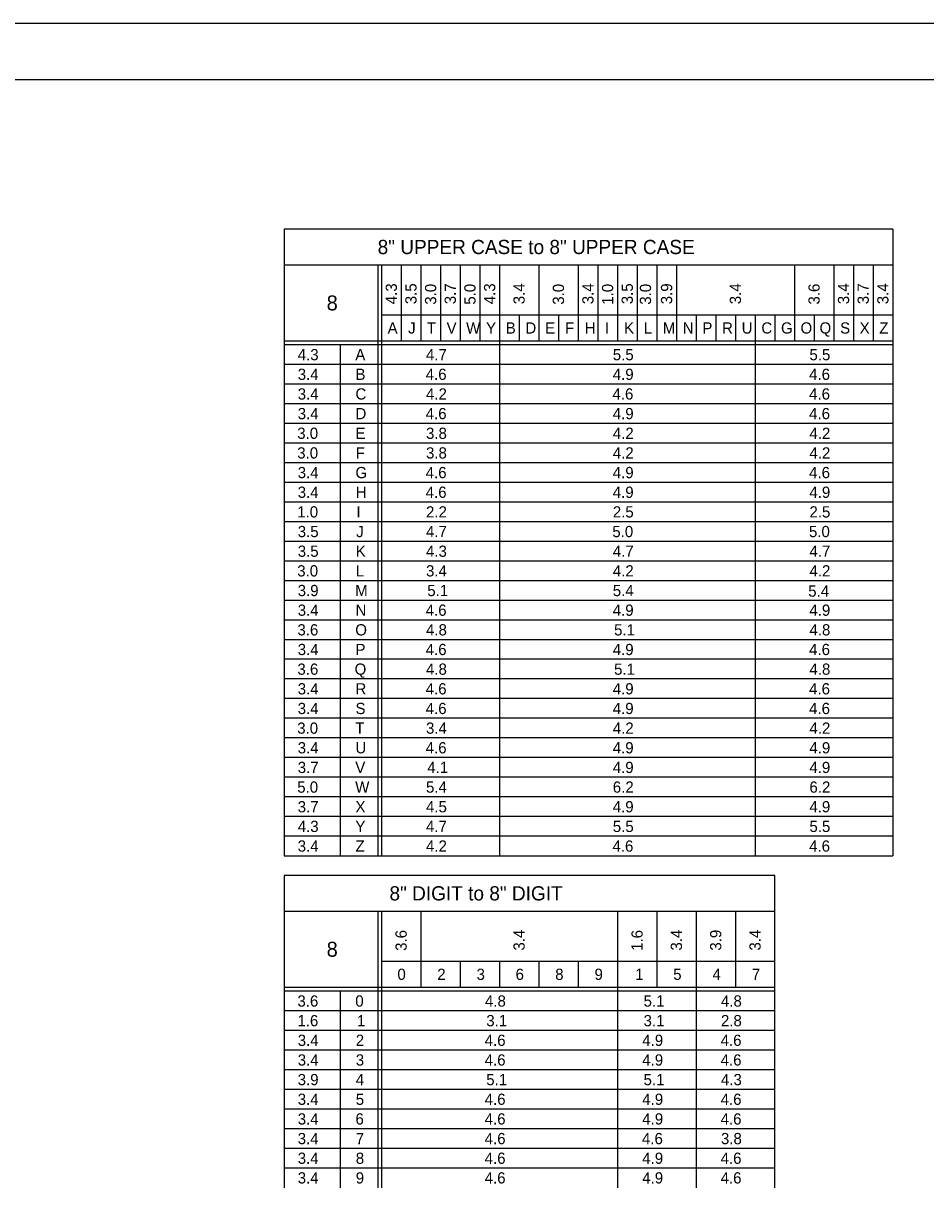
# Model space of a CAD drawing. Extents: x 638421 to 641849, y 297270 to 299646.
# Drawn here: x 641226.4 to 641467.4, y 299334.6 to 299645.6 of the extents above; entities that cross this region are included whole.
import ezdxf

# ---------------------------------------------------------------- set-up
doc = ezdxf.new("R2010")
doc.units = 0
for name, color, linetype in [('1', 7, 'Continuous'), ('2', 7, 'Continuous'), ('XCS-GRID-HVGL', 7, 'Continuous')]:
    doc.layers.add(name, color=color, linetype=linetype)

msp = doc.modelspace()

# ---------------------------------------------------------------- linework, layer by layer
at = {"layer": '1'}
msp.add_line((640984.31, 299630.63), (641770.31, 299630.63), dxfattribs=at)
at = {"layer": '2'}
for p, q in [((641458.56, 299590.63), (641296.06, 299590.63)), ((641296.06, 299590.63), (641296.06, 299423.25)), ((641458.56, 299590.63), (641458.56, 299423.25)), ((641296.06, 299581.13), (641458.56, 299581.13)), ((641321.06, 299581.13), (641321.06, 299423.25)), ((641322.06, 299581.13), (641322.06, 299423.25)), ((641327.31, 299581.13), (641327.31, 299560.75)), ((641332.56, 299581.13), (641332.56, 299560.75)), ((641337.81, 299581.13), (641337.81, 299560.75)), ((641343.06, 299581.13), (641343.06, 299560.75)), ((641348.31, 299581.13), (641348.31, 299560.75)), ((641353.56, 299581.13), (641353.56, 299423.25)), ((641364.06, 299581.13), (641364.06, 299560.75)), ((641374.56, 299581.13), (641374.56, 299560.75)), ((641379.81, 299581.13), (641379.81, 299560.75)), ((641385.06, 299581.13), (641385.06, 299560.75)), ((641390.31, 299581.13), (641390.31, 299560.75)), ((641395.56, 299581.13), (641395.56, 299560.75)), ((641400.81, 299581.13), (641400.81, 299560.75)), ((641432.31, 299581.13), (641432.31, 299560.75)), ((641442.81, 299581.13), (641442.81, 299560.75)), ((641448.06, 299581.13), (641448.06, 299560.75)), ((641453.31, 299581.13), (641453.31, 299560.75)), ((641322.06, 299567.75), (641458.56, 299567.75)), ((641358.81, 299567.75), (641358.81, 299560.75)), ((641369.31, 299567.75), (641369.31, 299560.75)), ((641406.06, 299567.75), (641406.06, 299560.75)), ((641411.31, 299567.75), (641411.31, 299560.75)), ((641416.56, 299567.75), (641416.56, 299560.75)), ((641416.56, 299567.75), (641416.56, 299560.75)), ((641421.81, 299567.75), (641421.81, 299423.25)), ((641427.06, 299567.75), (641427.06, 299560.75)), ((641437.56, 299567.75), (641437.56, 299560.75)), ((641458.56, 299560.75), (641296.06, 299560.75)), ((641458.56, 299559.75), (641296.06, 299559.75)), ((641311.06, 299559.75), (641311.06, 299423.25)), ((641458.56, 299554.5), (641296.06, 299554.5)), ((641458.56, 299549.25), (641296.06, 299549.25)), ((641458.56, 299544), (641296.06, 299544)), ((641458.56, 299538.75), (641296.06, 299538.75)), ((641458.56, 299533.5), (641296.06, 299533.5)), ((641458.56, 299528.25), (641296.06, 299528.25)), ((641458.56, 299523), (641296.06, 299523)), ((641458.56, 299517.75), (641296.06, 299517.75)), ((641458.56, 299512.5), (641296.06, 299512.5)), ((641458.56, 299507.25), (641296.06, 299507.25)), ((641458.56, 299502), (641296.06, 299502)), ((641458.56, 299496.75), (641296.06, 299496.75)), ((641458.56, 299491.5), (641296.06, 299491.5)), ((641458.56, 299486.25), (641296.06, 299486.25)), ((641458.56, 299481), (641296.06, 299481)), ((641458.56, 299475.75), (641296.06, 299475.75)), ((641458.56, 299470.5), (641296.06, 299470.5)), ((641458.56, 299465.25), (641296.06, 299465.25)), ((641458.56, 299460), (641296.06, 299460)), ((641458.56, 299454.75), (641296.06, 299454.75)), ((641458.56, 299449.5), (641296.06, 299449.5)), ((641458.56, 299444.25), (641296.06, 299444.25)), ((641458.56, 299439), (641296.06, 299439)), ((641458.56, 299433.75), (641296.06, 299433.75)), ((641458.56, 299428.5), (641296.06, 299428.5)), ((641296.06, 299423.25), (641296.06, 299423.25)), ((641296.06, 299423.25), (641458.56, 299423.25)), ((641427.06, 299418), (641296.06, 299418)), ((641296.06, 299418), (641296.06, 299334.63)), ((641427.06, 299334.63), (641427.06, 299418)), ((641296.06, 299408.5), (641427.06, 299408.5)), ((641321.06, 299408.5), (641321.06, 299334.63)), ((641322.06, 299408.5), (641322.06, 299334.63)), ((641332.56, 299408.5), (641332.56, 299388.13)), ((641385.06, 299408.5), (641385.06, 299334.63)), ((641395.56, 299408.5), (641395.56, 299388.13)), ((641406.06, 299408.5), (641406.06, 299334.63)), ((641416.56, 299408.5), (641416.56, 299388.13)), ((641322.06, 299395.13), (641427.06, 299395.13)), ((641343.06, 299395.13), (641343.06, 299388.13)), ((641353.56, 299395.13), (641353.56, 299388.13)), ((641364.06, 299395.13), (641364.06, 299388.13)), ((641374.56, 299395.13), (641374.56, 299388.13)), ((641427.06, 299388.13), (641296.06, 299388.13)), ((641427.06, 299387.13), (641296.06, 299387.13)), ((641311.06, 299387.13), (641311.06, 299334.63)), ((641427.06, 299381.88), (641296.06, 299381.88)), ((641427.06, 299376.63), (641296.06, 299376.63)), ((641427.06, 299371.38), (641296.06, 299371.38)), ((641427.06, 299366.13), (641296.06, 299366.13)), ((641427.06, 299360.88), (641296.06, 299360.88)), ((641427.06, 299355.63), (641296.06, 299355.63)), ((641427.06, 299350.38), (641296.06, 299350.38)), ((641427.06, 299345.13), (641296.06, 299345.13)), ((641427.06, 299339.88), (641296.06, 299339.88))]:
    msp.add_line(p, q, dxfattribs=at)
at = {"layer": 'XCS-GRID-HVGL'}
msp.add_lwpolyline([(640944.31, 299645.63), (641785.31, 299645.63), (641785.31, 299051.63), (640944.31, 299051.63)], close=True, dxfattribs=at)

# ---------------------------------------------------------------- texts
at = {"layer": '2'}
for s, height, p in [('8" UPPER CASE to 8" UPPER CASE', 3.8, (641321.05, 299583.98)), ('8', 4, (641307.43, 299568.94)), ('A', 3, (641323.71, 299562.75)), ('J', 3, (641329.19, 299562.75)), ('T', 3, (641334.19, 299562.75)), ('V', 3, (641339.46, 299562.75)), ('W', 3, (641344.68, 299562.75)), ('Y', 3, (641349.99, 299562.75)), ('B', 3, (641355.25, 299562.75)), ('D', 3, (641360.5, 299562.75)), ('E', 3, (641365.77, 299562.75)), ('F', 3, (641371.07, 299562.75)), ('H', 3, (641376.34, 299562.75)), ('I', 3, (641381.75, 299562.75)), ('K', 3, (641386.84, 299562.75)), ('L', 3, (641392.09, 299562.75)), ('M', 3, (641397.18, 299562.75)), ('N', 3, (641402.5, 299562.75)), ('P', 3, (641407.75, 299562.75)), ('R', 3, (641413, 299562.75)), ('U', 3, (641418.24, 299562.75)), ('C', 3, (641423.5, 299562.75)), ('G', 3, (641428.75, 299562.75)), ('O', 3, (641433.96, 299562.75)), ('Q', 3, (641439.03, 299562.75)), ('S', 3, (641444.52, 299562.75)), ('X', 3, (641449.74, 299562.75)), ('Z', 3, (641455, 299562.75)), ('4.3', 3, (641299.71, 299555.63)), ('A', 3, (641315.08, 299555.63)), ('4.7', 3, (641333.96, 299555.63)), ('5.5', 3, (641383.84, 299555.63)), ('5.5', 3, (641436.34, 299555.63)), ('3.4', 3, (641299.71, 299550.38)), ('B', 3, (641315.13, 299550.38)), ('4.6', 3, (641333.88, 299550.38)), ('4.9', 3, (641383.82, 299550.38)), ('4.6', 3, (641436.25, 299550.38)), ('3.4', 3, (641299.71, 299545.13)), ('C', 3, (641315.13, 299545.13)), ('4.2', 3, (641333.96, 299545.13)), ('4.6', 3, (641383.75, 299545.13)), ('4.6', 3, (641436.25, 299545.13)), ('3.4', 3, (641299.71, 299539.88)), ('D', 3, (641315.13, 299539.88)), ('4.6', 3, (641333.88, 299539.88)), ('4.9', 3, (641383.82, 299539.88)), ('4.6', 3, (641436.25, 299539.88)), ('3.0', 3, (641299.58, 299534.63)), ('E', 3, (641315.14, 299534.63)), ('3.8', 3, (641333.96, 299534.63)), ('4.2', 3, (641383.84, 299534.63)), ('4.2', 3, (641436.34, 299534.63)), ('3.0', 3, (641299.58, 299529.38)), ('F', 3, (641315.2, 299529.38)), ('3.8', 3, (641333.96, 299529.38)), ('4.2', 3, (641383.84, 299529.38)), ('4.2', 3, (641436.34, 299529.38)), ('3.4', 3, (641299.71, 299524.13)), ('G', 3, (641315.13, 299524.13)), ('4.6', 3, (641333.88, 299524.13)), ('4.9', 3, (641383.82, 299524.13)), ('4.6', 3, (641436.25, 299524.13)), ('3.4', 3, (641299.71, 299518.88)), ('H', 3, (641315.21, 299518.88)), ('4.6', 3, (641333.88, 299518.88)), ('4.9', 3, (641383.82, 299518.88)), ('4.9', 3, (641436.32, 299518.88)), ('1.0', 3, (641299.58, 299513.63)), ('I', 3, (641315.38, 299513.63)), ('2.2', 3, (641333.96, 299513.63)), ('2.5', 3, (641383.84, 299513.63)), ('2.5', 3, (641436.34, 299513.63)), ('3.5', 3, (641299.71, 299508.38)), ('J', 3, (641315.32, 299508.38)), ('4.7', 3, (641333.96, 299508.38)), ('5.0', 3, (641383.71, 299508.38)), ('5.0', 3, (641436.21, 299508.38)), ('3.5', 3, (641299.71, 299503.13)), ('K', 3, (641315.21, 299503.13)), ('4.3', 3, (641333.96, 299503.13)), ('4.7', 3, (641383.84, 299503.13)), ('4.7', 3, (641436.34, 299503.13)), ('3.0', 3, (641299.58, 299497.88)), ('L', 3, (641315.21, 299497.88)), ('3.4', 3, (641333.96, 299497.88)), ('4.2', 3, (641383.84, 299497.88)), ('4.2', 3, (641436.34, 299497.88)), ('3.9', 3, (641299.7, 299492.63)), ('M', 3, (641315.06, 299492.63)), ('5.1', 3, (641334.3, 299492.63)), ('5.4', 3, (641383.84, 299492.63)), ('5.4', 3, (641436.01, 299492.48)), ('3.4', 3, (641299.71, 299487.38)), ('N', 3, (641315.13, 299487.38)), ('4.6', 3, (641333.88, 299487.38)), ('4.9', 3, (641383.82, 299487.38)), ('4.9', 3, (641436.32, 299487.38)), ('3.6', 3, (641299.63, 299482.13)), ('O', 3, (641315.08, 299482.13)), ('4.8', 3, (641333.96, 299482.13)), ('5.1', 3, (641384.18, 299482.13)), ('4.8', 3, (641436.34, 299482.13)), ('3.4', 3, (641299.71, 299476.88)), ('P', 3, (641315.13, 299476.88)), ('4.6', 3, (641333.88, 299476.88)), ('4.9', 3, (641383.82, 299476.88)), ('4.6', 3, (641436.25, 299476.88)), ('3.6', 3, (641299.63, 299471.63)), ('Q', 3, (641314.9, 299471.63)), ('4.8', 3, (641333.96, 299471.63)), ('5.1', 3, (641384.18, 299471.63)), ('4.8', 3, (641436.34, 299471.63)), ('3.4', 3, (641299.71, 299466.38)), ('R', 3, (641315.13, 299466.38)), ('4.6', 3, (641333.88, 299466.38)), ('4.9', 3, (641383.82, 299466.38)), ('4.6', 3, (641436.25, 299466.38)), ('3.4', 3, (641299.71, 299461.13)), ('S', 3, (641315.14, 299461.13)), ('4.6', 3, (641333.88, 299461.13)), ('4.9', 3, (641383.82, 299461.13)), ('4.6', 3, (641436.25, 299461.13)), ('3.0', 3, (641299.58, 299455.88)), ('T', 3, (641315.07, 299455.88)), ('3.4', 3, (641333.96, 299455.88)), ('4.2', 3, (641383.84, 299455.88)), ('4.2', 3, (641436.34, 299455.88)), ('3.4', 3, (641299.71, 299450.63)), ('U', 3, (641315.12, 299450.63)), ('4.6', 3, (641333.88, 299450.63)), ('4.9', 3, (641383.82, 299450.63)), ('4.9', 3, (641436.32, 299450.63)), ('3.7', 3, (641299.71, 299445.38)), ('V', 3, (641315.08, 299445.38)), ('4.1', 3, (641334.3, 299445.38)), ('4.9', 3, (641383.82, 299445.38)), ('4.9', 3, (641436.32, 299445.38)), ('5.0', 3, (641299.58, 299440.13)), ('W', 3, (641315.06, 299440.13)), ('5.4', 3, (641333.96, 299440.13)), ('6.2', 3, (641383.84, 299440.13)), ('6.2', 3, (641436.34, 299440.13)), ('3.7', 3, (641299.71, 299434.88)), ('X', 3, (641315.12, 299434.88)), ('4.5', 3, (641333.96, 299434.88)), ('4.9', 3, (641383.82, 299434.88)), ('4.9', 3, (641436.32, 299434.88)), ('4.3', 3, (641299.71, 299429.63)), ('Y', 3, (641315.12, 299429.63)), ('4.7', 3, (641333.96, 299429.63)), ('5.5', 3, (641383.84, 299429.63)), ('5.5', 3, (641436.34, 299429.63)), ('3.4', 3, (641299.71, 299424.38)), ('Z', 3, (641315.13, 299424.38)), ('4.2', 3, (641333.96, 299424.38)), ('4.6', 3, (641383.75, 299424.38)), ('4.6', 3, (641436.25, 299424.38)), ('8" DIGIT to 8" DIGIT', 3.8, (641324.21, 299411.35)), ('8', 4, (641307.43, 299396.31)), ('0', 3, (641326.33, 299390.13)), ('2', 3, (641336.96, 299390.13)), ('3', 3, (641347.46, 299390.13)), ('6', 3, (641357.88, 299390.13)), ('8', 3, (641368.46, 299390.13)), ('9', 3, (641378.95, 299390.13)), ('1', 3, (641389.8, 299390.13)), ('5', 3, (641399.96, 299390.13)), ('4', 3, (641410.46, 299390.13)), ('7', 3, (641420.96, 299390.13)), ('3.6', 3, (641299.63, 299383)), ('0', 3, (641315.08, 299383)), ('4.8', 3, (641349.71, 299383)), ('5.1', 3, (641392.05, 299383)), ('4.8', 3, (641412.71, 299383)), ('1.6', 3, (641299.63, 299377.75)), ('1', 3, (641315.55, 299377.75)), ('3.1', 3, (641350.05, 299377.75)), ('3.1', 3, (641392.05, 299377.75)), ('2.8', 3, (641412.71, 299377.75)), ('3.4', 3, (641299.71, 299372.5)), ('2', 3, (641315.21, 299372.5)), ('4.6', 3, (641349.63, 299372.5)), ('4.9', 3, (641391.7, 299372.5)), ('4.6', 3, (641412.63, 299372.5)), ('3.4', 3, (641299.71, 299367.25)), ('3', 3, (641315.21, 299367.25)), ('4.6', 3, (641349.63, 299367.25)), ('4.9', 3, (641391.7, 299367.25)), ('4.6', 3, (641412.63, 299367.25)), ('3.9', 3, (641299.7, 299362)), ('4', 3, (641315.21, 299362)), ('5.1', 3, (641350.05, 299362)), ('5.1', 3, (641392.05, 299362)), ('4.3', 3, (641412.71, 299362)), ('3.4', 3, (641299.71, 299356.75)), ('5', 3, (641315.21, 299356.75)), ('4.6', 3, (641349.63, 299356.75)), ('4.9', 3, (641391.7, 299356.75)), ('4.6', 3, (641412.63, 299356.75)), ('3.4', 3, (641299.71, 299351.5)), ('6', 3, (641315.13, 299351.5)), ('4.6', 3, (641349.63, 299351.5)), ('4.9', 3, (641391.7, 299351.5)), ('4.6', 3, (641412.63, 299351.5)), ('3.4', 3, (641299.71, 299346.25)), ('7', 3, (641315.21, 299346.25)), ('4.6', 3, (641349.63, 299346.25)), ('4.6', 3, (641391.63, 299346.25)), ('3.8', 3, (641412.71, 299346.25)), ('3.4', 3, (641299.71, 299341)), ('8', 3, (641315.21, 299341)), ('4.6', 3, (641349.63, 299341)), ('4.9', 3, (641391.7, 299341)), ('4.6', 3, (641412.63, 299341)), ('3.4', 3, (641299.71, 299335.75)), ('9', 3, (641315.2, 299335.75)), ('4.6', 3, (641349.63, 299335.75)), ('4.9', 3, (641391.7, 299335.75)), ('4.6', 3, (641412.63, 299335.75))]:
    msp.add_text(s, height=height, dxfattribs=at).set_placement(p)
for s, p in [('4.3', (641326.19, 299570.59)), ('3.5', (641331.44, 299570.59)), ('3.0', (641336.69, 299570.46)), ('3.7', (641341.94, 299570.59)), ('5.0', (641347.19, 299570.46)), ('4.3', (641352.44, 299570.59)), ('3.4', (641360.31, 299570.59)), ('3.0', (641370.81, 299570.46)), ('3.4', (641378.69, 299570.59)), ('1.0', (641383.94, 299570.46)), ('3.5', (641389.19, 299570.59)), ('3.0', (641394.05, 299570.46)), ('3.9', (641399.69, 299570.58)), ('3.4', (641418.06, 299570.59)), ('3.6', (641439.06, 299570.51)), ('3.4', (641446.94, 299570.59)), ('3.7', (641452.19, 299570.59)), ('3.4', (641457.44, 299570.59)), ('3.6', (641328.81, 299397.88)), ('3.4', (641360.31, 299397.96)), ('1.6', (641391.81, 299397.88)), ('3.4', (641402.31, 299397.96)), ('3.9', (641412.81, 299397.95)), ('3.4', (641423.31, 299397.96))]:
    msp.add_text(s, height=3, rotation=90, dxfattribs=at).set_placement(p)

doc.saveas('drawing.dxf')
